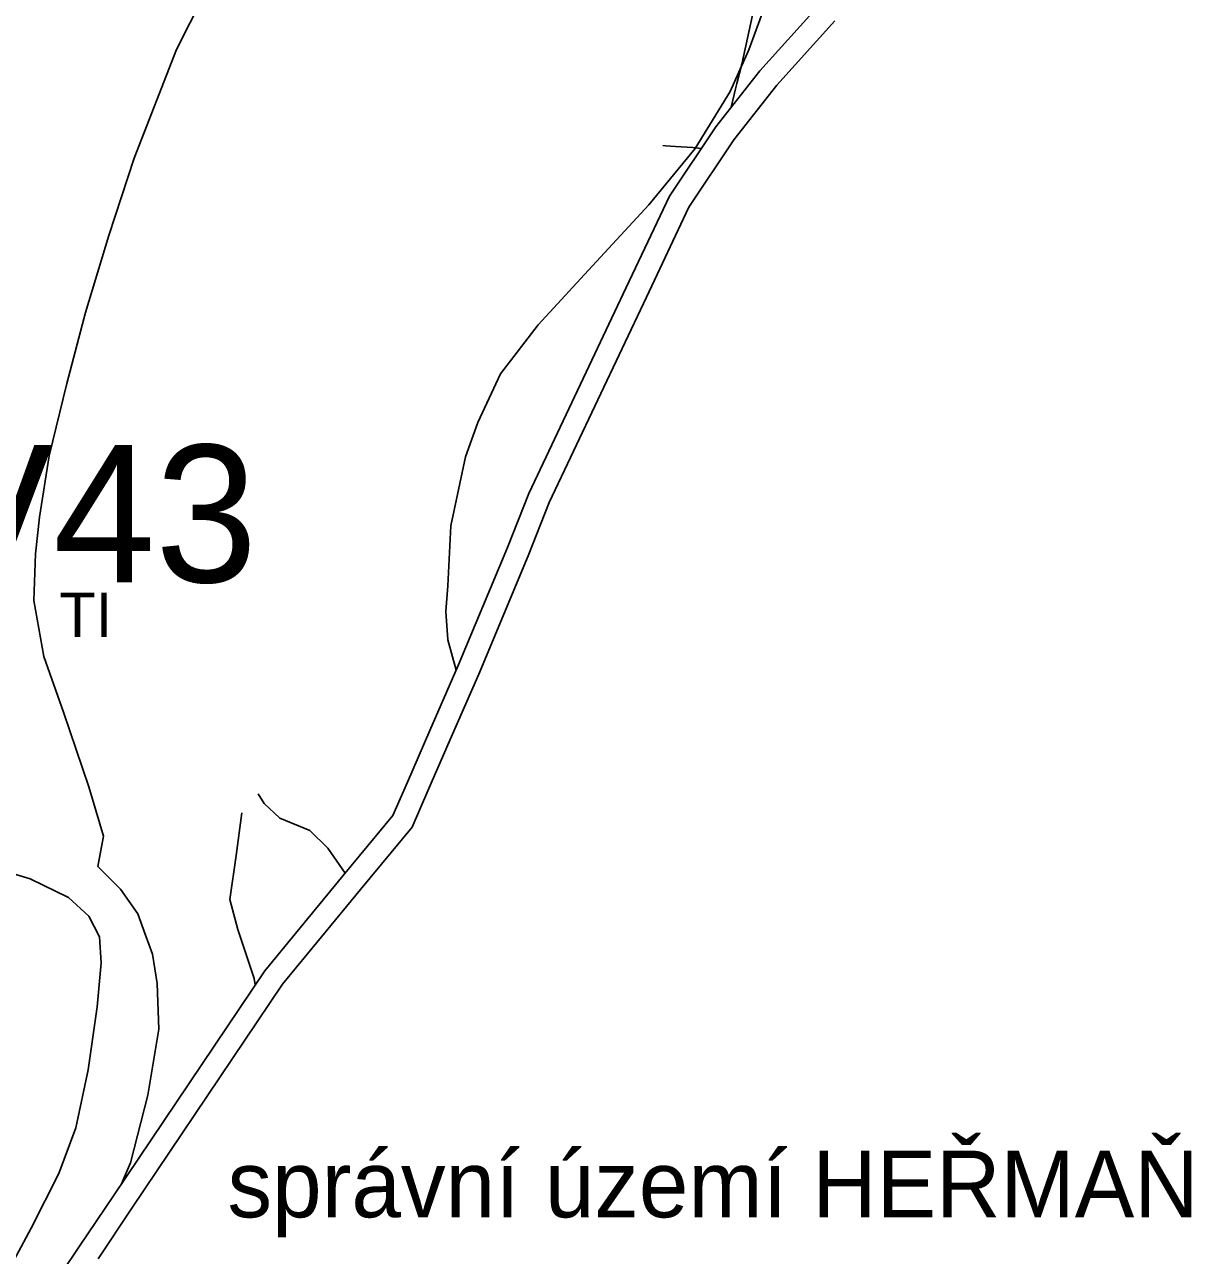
# Model space of a CAD drawing. Extents: x -758499 to -754160, y -1175205 to -1172032.
# Drawn here: x -755466 to -755203.6, y -1173497.6 to -1173220.7 of the extents above; entities that cross this region are included whole.
import ezdxf

# ---------------------------------------------------------------- set-up
doc = ezdxf.new("R2010")
doc.units = 0
for name, color, linetype in [('A041_BPEJ_p', 7, 'Continuous'), ('A073_ElVed_l_NN', 7, 'Continuous'), ('A073_ElVed_l_VN', 7, 'Continuous'), ('A118_ZamZUR_TI_p', 7, 'Continuous'), ('HRANICE katastrální - názvy', 7, 'Continuous'), ('HRANICE zastavěného území', 7, 'Continuous'), ('HRANICE zastavěného území - podbarvení', 7, 'Continuous'), ('HRANICE řešeného území', 7, 'Continuous'), ('indexy RZV_TYP_1', 7, 'Continuous'), ('PLOCHY TI technické infrastruktury', 7, 'Continuous'), ('vrstevnice', 7, 'Continuous')]:
    doc.layers.add(name, color=color, linetype=linetype)

msp = doc.modelspace()

# ---------------------------------------------------------------- linework, layer by layer
at = {"layer": 'A041_BPEJ_p'}
msp.add_lwpolyline([(-755231.82, -1173127.68), (-755232.16, -1173128.63), (-755232.49, -1173129.56), (-755238.76, -1173147.14), (-755259.44, -1173183.9), (-755265.44, -1173194.57), (-755287.41, -1173216.37), (-755300.69, -1173231.06), (-755310.54, -1173243.65), (-755320.97, -1173259.29), (-755330.69, -1173279.83), (-755352.64, -1173326.19), (-755357.39, -1173338.3), (-755368.5, -1173364.88), (-755374.88, -1173379.53), (-755379.92, -1173391.1), (-755383.2, -1173398.64), (-755394.35, -1173412.14), (-755412.03, -1173433.56), (-755446.05, -1173484.21), (-755453.67, -1173495.56), (-755457.81, -1173501.72), (-755420.13, -1173514.56)], dxfattribs=at)
at = {"layer": 'A073_ElVed_l_NN'}
for p, q in [((-755304.73, -1173229.55), (-755300.75, -1173211.55)), ((-755305.8, -1173233.91), (-755304.73, -1173229.55)), ((-755306.1, -1173235.11), (-755305.8, -1173233.91))]:
    msp.add_line(p, q, dxfattribs=at)
at = {"layer": 'A073_ElVed_l_VN'}
for p, q in [((-755307.08, -1173239.23), (-755306.1, -1173235.11)), ((-755322.51, -1173247.91), (-755321.86, -1173247.99)), ((-755321.86, -1173247.99), (-755319.65, -1173248.1)), ((-755319.65, -1173248.1), (-755315.73, -1173248.36)), ((-755315.73, -1173248.36), (-755313.79, -1173248.52))]:
    msp.add_line(p, q, dxfattribs=at)
at = {"layer": 'HRANICE zastavěného území'}
msp.add_lwpolyline([(-755287.41, -1173216.37), (-755300.69, -1173231.06), (-755310.54, -1173243.65), (-755320.97, -1173259.29), (-755330.69, -1173279.83), (-755352.64, -1173326.19), (-755357.39, -1173338.3), (-755368.5, -1173364.88), (-755374.88, -1173379.53), (-755379.92, -1173391.1), (-755383.2, -1173398.64), (-755394.35, -1173412.14), (-755412.03, -1173433.56), (-755446.05, -1173484.21), (-755453.67, -1173495.56), (-755457.81, -1173501.72)], dxfattribs=at)
at = {"layer": 'HRANICE zastavěného území - podbarvení'}
msp.add_lwpolyline([(-755287.41, -1173216.37), (-755300.69, -1173231.06), (-755310.54, -1173243.65), (-755320.97, -1173259.29), (-755330.69, -1173279.83), (-755352.64, -1173326.19), (-755357.39, -1173338.3), (-755368.5, -1173364.88), (-755374.88, -1173379.53), (-755379.92, -1173391.1), (-755383.2, -1173398.64), (-755394.35, -1173412.14), (-755412.03, -1173433.56), (-755446.05, -1173484.21), (-755453.67, -1173495.56), (-755457.81, -1173501.72)], dxfattribs=at)
at = {"layer": 'HRANICE řešeného území'}
for points in [[(-755287.41, -1173216.37), (-755300.69, -1173231.06), (-755310.54, -1173243.65), (-755320.97, -1173259.29), (-755330.69, -1173279.83), (-755352.64, -1173326.19), (-755357.39, -1173338.3), (-755368.5, -1173364.88), (-755374.88, -1173379.53), (-755379.92, -1173391.1), (-755383.2, -1173398.64), (-755394.35, -1173412.14), (-755412.03, -1173433.56), (-755446.05, -1173484.21), (-755453.67, -1173495.56), (-755457.81, -1173501.72)], [(-755283.79, -1173219.82), (-755296.86, -1173234.28), (-755306.49, -1173246.58), (-755316.61, -1173261.76), (-755326.17, -1173281.97), (-755348.05, -1173328.18), (-755352.76, -1173340.18), (-755363.9, -1173366.84), (-755370.3, -1173381.53), (-755375.34, -1173393.1), (-755378.9, -1173401.28), (-755390.49, -1173415.32), (-755408.02, -1173436.55), (-755441.9, -1173487), (-755449.52, -1173498.35)]]:
    msp.add_lwpolyline(points, dxfattribs=at)
at = {"layer": 'PLOCHY TI technické infrastruktury'}
msp.add_lwpolyline([(-755287.41, -1173216.37), (-755300.69, -1173231.06), (-755310.54, -1173243.65), (-755320.97, -1173259.29), (-755330.69, -1173279.83), (-755352.64, -1173326.19), (-755357.39, -1173338.3), (-755368.5, -1173364.88), (-755374.88, -1173379.53), (-755379.92, -1173391.1), (-755383.2, -1173398.64), (-755394.35, -1173412.14), (-755412.03, -1173433.56), (-755446.05, -1173484.21), (-755453.67, -1173495.56), (-755457.81, -1173501.72)], dxfattribs=at)
at = {"layer": 'vrstevnice'}
for p, q in [((-755425.27, -1173213.22), (-755431.85, -1173226.25)), ((-755425.27, -1173213.22), (-755431.85, -1173226.25)), ((-755299.85, -1173217.38), (-755303.13, -1173226.36)), ((-755299.85, -1173217.38), (-755303.13, -1173226.36)), ((-755431.85, -1173226.25), (-755441.43, -1173250.72)), ((-755431.85, -1173226.25), (-755441.43, -1173250.72)), ((-755303.13, -1173226.36), (-755307.33, -1173235.71)), ((-755303.13, -1173226.36), (-755307.33, -1173235.71)), ((-755307.33, -1173235.71), (-755315.19, -1173248.54)), ((-755307.33, -1173235.71), (-755315.19, -1173248.54)), ((-755315.19, -1173248.54), (-755325.61, -1173261.2)), ((-755315.19, -1173248.54), (-755325.61, -1173261.2)), ((-755441.43, -1173250.72), (-755447.09, -1173268.15)), ((-755441.43, -1173250.72), (-755447.09, -1173268.15)), ((-755325.61, -1173261.2), (-755340.13, -1173276.87)), ((-755325.61, -1173261.2), (-755340.13, -1173276.87)), ((-755447.09, -1173268.15), (-755452.33, -1173285.43)), ((-755447.09, -1173268.15), (-755452.33, -1173285.43)), ((-755340.13, -1173276.87), (-755350.55, -1173288.24)), ((-755340.13, -1173276.87), (-755350.55, -1173288.24)), ((-755452.33, -1173285.43), (-755456.53, -1173301.4)), ((-755452.33, -1173285.43), (-755456.53, -1173301.4)), ((-755350.55, -1173288.24), (-755359.02, -1173299.22)), ((-755350.55, -1173288.24), (-755359.02, -1173299.22)), ((-755359.02, -1173299.22), (-755364.13, -1173310.21)), ((-755359.02, -1173299.22), (-755364.13, -1173310.21)), ((-755456.53, -1173301.4), (-755460.54, -1173317.73)), ((-755456.53, -1173301.4), (-755460.54, -1173317.73)), ((-755364.13, -1173310.21), (-755366.86, -1173317.91)), ((-755364.13, -1173310.21), (-755366.86, -1173317.91)), ((-755460.54, -1173317.73), (-755462.72, -1173331.49)), ((-755460.54, -1173317.73), (-755462.72, -1173331.49)), ((-755366.86, -1173317.91), (-755370.14, -1173333.49)), ((-755366.86, -1173317.91), (-755370.14, -1173333.49)), ((-755462.72, -1173331.49), (-755463.62, -1173339.75)), ((-755462.72, -1173331.49), (-755463.62, -1173339.75)), ((-755370.14, -1173333.49), (-755370.86, -1173346.96)), ((-755370.14, -1173333.49), (-755370.86, -1173346.96)), ((-755463.62, -1173339.75), (-755463.94, -1173350.23)), ((-755463.62, -1173339.75), (-755463.94, -1173350.23)), ((-755370.86, -1173346.96), (-755371.3, -1173352.73)), ((-755370.86, -1173346.96), (-755371.3, -1173352.73)), ((-755463.94, -1173350.23), (-755461.72, -1173362.89)), ((-755463.94, -1173350.23), (-755461.72, -1173362.89)), ((-755371.3, -1173352.73), (-755370.83, -1173359.11)), ((-755371.3, -1173352.73), (-755370.83, -1173359.11)), ((-755370.83, -1173359.11), (-755368.97, -1173365.97)), ((-755370.83, -1173359.11), (-755368.97, -1173365.97)), ((-755461.72, -1173362.89), (-755457.3, -1173375.36)), ((-755461.72, -1173362.89), (-755457.3, -1173375.36)), ((-755457.3, -1173375.36), (-755451.59, -1173392.22)), ((-755457.3, -1173375.36), (-755451.59, -1173392.22)), ((-755451.59, -1173392.22), (-755448.33, -1173403.31)), ((-755451.59, -1173392.22), (-755448.33, -1173403.31)), ((-755413.51, -1173393.75), (-755412.13, -1173395.95)), ((-755413.51, -1173393.75), (-755412.13, -1173395.95)), ((-755417.2, -1173398.06), (-755418.44, -1173407.65)), ((-755417.2, -1173398.06), (-755418.44, -1173407.65)), ((-755412.13, -1173395.95), (-755408.64, -1173399.24)), ((-755412.13, -1173395.95), (-755408.64, -1173399.24)), ((-755408.64, -1173399.24), (-755401.86, -1173401.98)), ((-755408.64, -1173399.24), (-755401.86, -1173401.98)), ((-755448.33, -1173403.31), (-755449.6, -1173410.1)), ((-755448.33, -1173403.31), (-755449.6, -1173410.1)), ((-755401.86, -1173401.98), (-755397.82, -1173406)), ((-755401.86, -1173401.98), (-755397.82, -1173406)), ((-755397.82, -1173406), (-755393.91, -1173411.61)), ((-755397.82, -1173406), (-755393.91, -1173411.61)), ((-755418.44, -1173407.65), (-755419.89, -1173417.56)), ((-755418.44, -1173407.65), (-755419.89, -1173417.56)), ((-755472.65, -1173410.54), (-755464.83, -1173412.9)), ((-755449.6, -1173410.1), (-755444.46, -1173415.23)), ((-755449.6, -1173410.1), (-755444.46, -1173415.23)), ((-755464.83, -1173412.9), (-755456.2, -1173417.11)), ((-755456.2, -1173417.11), (-755451.6, -1173421.32)), ((-755444.46, -1173415.23), (-755440.6, -1173420.73)), ((-755444.46, -1173415.23), (-755440.6, -1173420.73)), ((-755419.89, -1173417.56), (-755418.06, -1173424.3)), ((-755419.89, -1173417.56), (-755418.06, -1173424.3)), ((-755451.6, -1173421.32), (-755449.21, -1173425.9)), ((-755440.6, -1173420.73), (-755438.94, -1173425.31)), ((-755440.6, -1173420.73), (-755438.94, -1173425.31)), ((-755449.21, -1173425.9), (-755448.83, -1173431.78)), ((-755438.94, -1173425.31), (-755437.31, -1173429.84)), ((-755438.94, -1173425.31), (-755437.31, -1173429.84)), ((-755418.06, -1173424.3), (-755414.38, -1173435.3)), ((-755418.06, -1173424.3), (-755414.38, -1173435.3)), ((-755437.31, -1173429.84), (-755436.2, -1173436.45)), ((-755437.31, -1173429.84), (-755436.2, -1173436.45)), ((-755448.83, -1173431.78), (-755449.73, -1173441.69)), ((-755436.2, -1173436.45), (-755435.82, -1173446.72)), ((-755436.2, -1173436.45), (-755435.82, -1173446.72)), ((-755414.38, -1173435.3), (-755414.18, -1173436.76)), ((-755414.38, -1173435.3), (-755414.18, -1173436.76)), ((-755449.73, -1173441.69), (-755451.73, -1173455.83)), ((-755435.82, -1173446.72), (-755438.36, -1173461.58)), ((-755435.82, -1173446.72), (-755438.36, -1173461.58)), ((-755451.73, -1173455.83), (-755454.49, -1173468.89)), ((-755438.36, -1173461.58), (-755442.19, -1173476.81)), ((-755438.36, -1173461.58), (-755442.19, -1173476.81)), ((-755454.49, -1173468.89), (-755458.33, -1173479.17)), ((-755442.19, -1173476.81), (-755444.26, -1173481.54)), ((-755442.19, -1173476.81), (-755444.26, -1173481.54)), ((-755458.33, -1173479.17), (-755464.55, -1173491.48)), ((-755464.55, -1173491.48), (-755472.61, -1173506.48))]:
    msp.add_line(p, q, dxfattribs=at)

# ---------------------------------------------------------------- texts
at = {"layer": 'A118_ZamZUR_TI_p'}
msp.add_text('V43', height=30.878, dxfattribs=at).set_placement((-755487.17, -1173346.14))
at = {"layer": 'HRANICE katastrální - názvy'}
msp.add_text('správní území HEŘMAŇ', height=15, dxfattribs=at).set_placement((-755420.41, -1173489.05))
at = {"layer": 'indexy RZV_TYP_1'}
msp.add_text('TI', height=10, dxfattribs=at).set_placement((-755458.22, -1173358.46))

doc.saveas('drawing.dxf')
